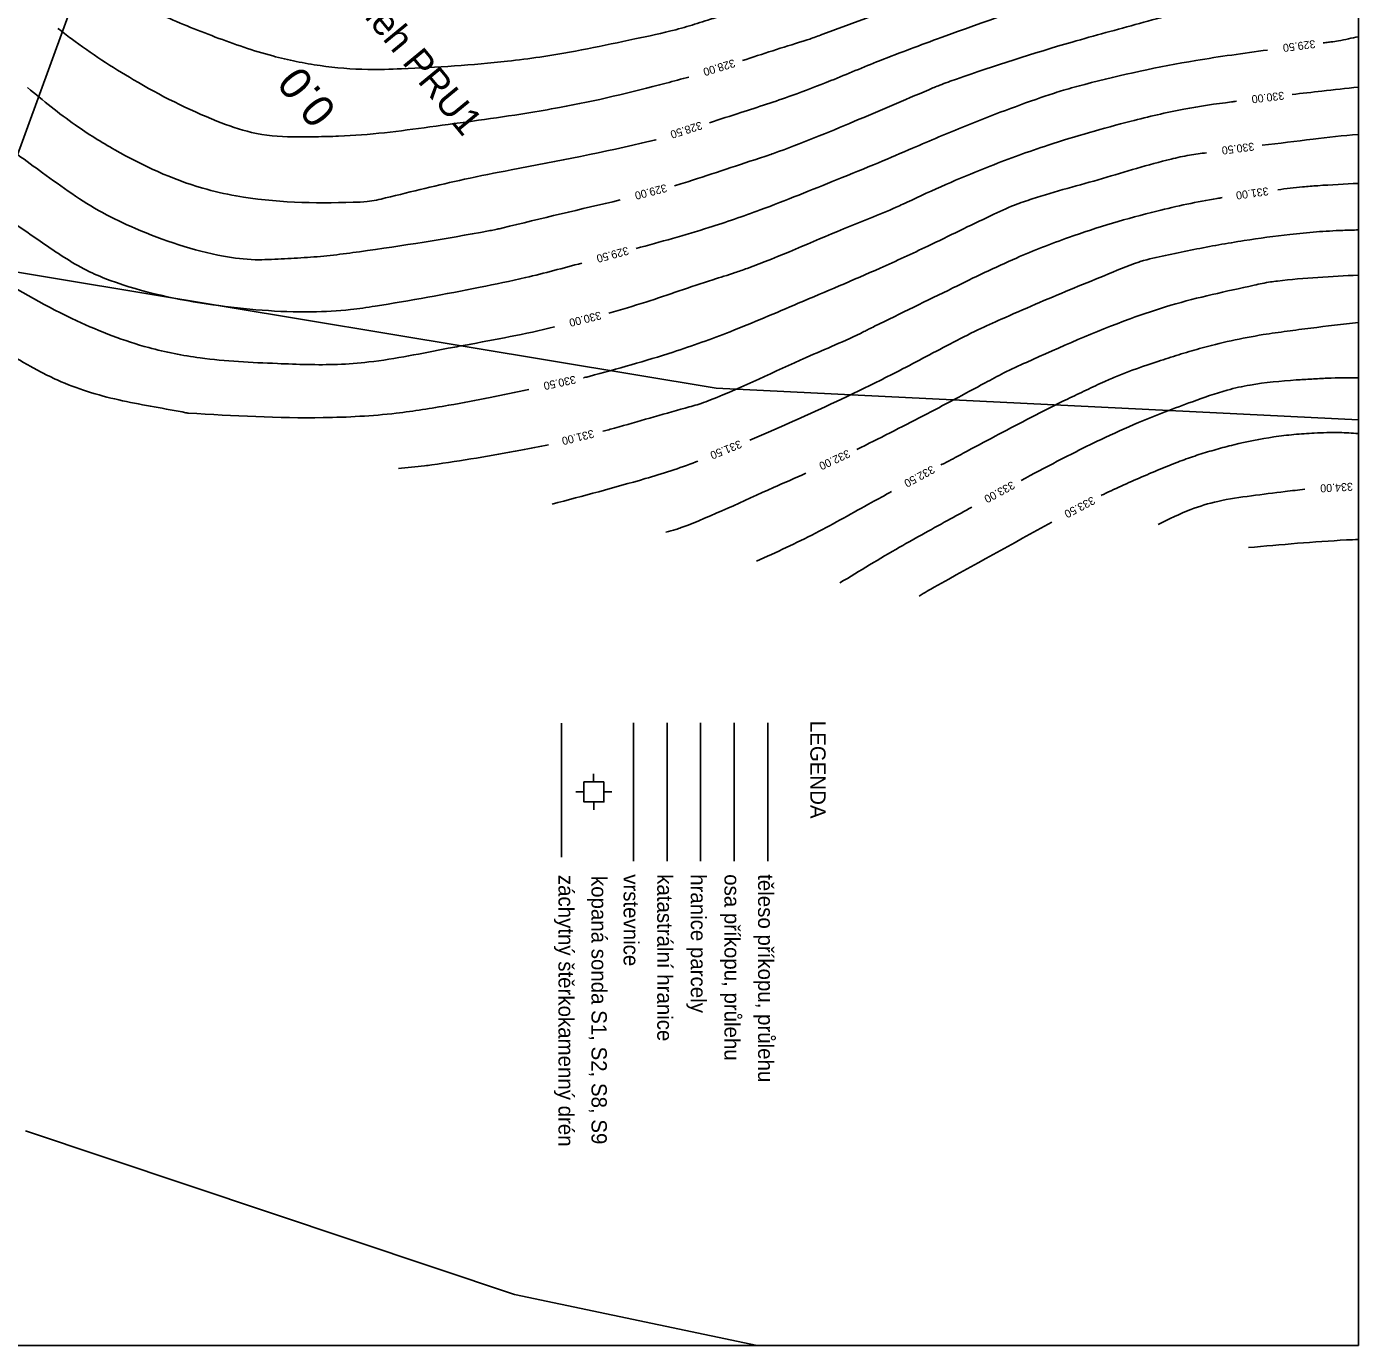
# Model space of a CAD drawing. Extents: x -564091 to -563943, y -1163604 to -1163394.
# Drawn here: x -564025.8 to -563942.6, y -1163603.9 to -1163521.5 of the extents above; entities that cross this region are included whole.
import ezdxf

# ---------------------------------------------------------------- set-up
doc = ezdxf.new("R2010")
doc.units = 0
for name, color, linetype in [('4', 7, 'Continuous'), ('_popis staničení PRU1', 7, 'Continuous'), ('_rám PRU1 a PRI1', 7, 'Continuous'), ('Hranice parcel', 7, 'Continuous'), ('Vrstva 24', 7, 'Continuous'), ('Vrstva 25', 7, 'Continuous'), ('Vrstva 26', 7, 'Continuous')]:
    doc.layers.add(name, color=color, linetype=linetype)

msp = doc.modelspace()

# ---------------------------------------------------------------- linework, layer by layer
at = {"layer": '_rám PRU1 a PRI1'}
for p, q in [((-563942.618, -1163603.908), (-563942.618, -1163393.908)), ((-563992.386, -1163565.031), (-563992.386, -1163573.399)), ((-563987.899, -1163565.001), (-563987.899, -1163573.654)), ((-563985.799, -1163565.001), (-563985.799, -1163573.654)), ((-563983.699, -1163565.001), (-563983.699, -1163573.654)), ((-563981.598, -1163565.001), (-563981.598, -1163573.654)), ((-563979.498, -1163565.001), (-563979.498, -1163573.654)), ((-563990.392, -1163568.702), (-563990.392, -1163568.202)), ((-563990.992, -1163569.315), (-563991.492, -1163569.315)), ((-563989.742, -1163569.327), (-563989.242, -1163569.327)), ((-563990.367, -1163569.952), (-563990.367, -1163570.452)), ((-564091.118, -1163603.908), (-563942.618, -1163603.908))]:
    msp.add_line(p, q, dxfattribs=at)
msp.add_lwpolyline([(-563989.742, -1163568.702), (-563989.742, -1163569.952), (-563990.992, -1163569.952), (-563990.992, -1163568.702)], close=True, dxfattribs=at)
at = {"layer": 'Hranice parcel'}
for points in [[(-564021.9, -1163513.74), (-564022.73, -1163519.5), (-564028.91, -1163536.42)], [(-564028.91, -1163536.42), (-563982.72, -1163544.1), (-563942.618, -1163546.064)], [(-563980.179, -1163603.908), (-563995.32, -1163600.73), (-564025.86, -1163590.51)]]:
    msp.add_lwpolyline(points, dxfattribs=at)
at = {"layer": 'Vrstva 24'}
for points in [[(-563981.09, -1163523.624), (-563977.297, -1163522.411), (-563977.044, -1163522.332), (-563976.888, -1163522.279), (-563976.122, -1163522.001), (-563967.965, -1163518.991), (-563964.546, -1163517.65), (-563963.719, -1163517.299), (-563962.899, -1163516.935), (-563962.079, -1163516.568), (-563961.256, -1163516.209), (-563958.806, -1163515.217), (-563955.507, -1163514.121), (-563954.271, -1163513.735), (-563953.033, -1163513.357), (-563951.794, -1163512.978), (-563950.56, -1163512.586), (-563949.842, -1163512.32), (-563948.534, -1163511.756), (-563947.231, -1163511.18), (-563945.929, -1163510.605), (-563944.62, -1163510.044), (-563942.618, -1163509.205)], [(-563985.34, -1163531.458), (-563984.8, -1163531.288), (-563980.022, -1163529.724), (-563979.493, -1163529.549), (-563979.15, -1163529.429), (-563974.083, -1163527.416), (-563969.443, -1163525.445), (-563968.766, -1163525.163), (-563967.716, -1163524.777), (-563960.498, -1163522.468), (-563958.395, -1163521.879), (-563956.289, -1163521.303), (-563954.183, -1163520.729), (-563952.079, -1163520.145), (-563951.956, -1163520.11), (-563951.901, -1163520.097), (-563950.485, -1163519.822), (-563949.067, -1163519.564), (-563946.237, -1163519.013), (-563945.87, -1163518.932)], [(-564023.856, -1163521.61), (-564023.008, -1163522.254), (-564019.131, -1163524.819), (-564013.91, -1163527.406), (-564011.75, -1163528.111), (-564009.173, -1163528.394), (-564007.742, -1163528.383), (-564006.309, -1163528.346), (-564003.45, -1163528.132), (-564000.607, -1163527.771), (-563994.561, -1163526.908), (-563992.517, -1163526.557), (-563985.848, -1163525.032), (-563984.436, -1163524.651)], [(-564027.878, -1163528.392), (-564024.804, -1163530.633), (-564021.062, -1163533.125), (-564019.008, -1163534.113), (-564013.494, -1163535.843), (-564011.523, -1163536.066), (-564009.893, -1163536.018), (-564008.263, -1163535.926), (-564006.633, -1163535.779), (-564005.008, -1163535.571), (-563996.957, -1163534.27), (-563996.575, -1163534.197), (-563996.412, -1163534.163), (-563996.109, -1163534.091), (-563988.728, -1163532.333)], [(-563947.656, -1163531.694), (-563946.1, -1163531.518), (-563945.153, -1163531.441), (-563942.618, -1163531.298)], [(-563989.803, -1163546.79), (-563989.07, -1163546.588), (-563984.665, -1163545.34), (-563983.671, -1163545.047), (-563983.074, -1163544.825), (-563977.1, -1163542.175), (-563973.501, -1163540.56), (-563973.207, -1163540.412), (-563972.833, -1163540.227), (-563967.943, -1163537.832), (-563963.975, -1163535.961), (-563960.714, -1163534.677), (-563955.196, -1163533.028), (-563951.439, -1163532.239), (-563951.12, -1163532.187)], [(-563973.953, -1163547.931), (-563969.797, -1163545.821), (-563965.936, -1163543.764), (-563964.762, -1163543.143), (-563963.355, -1163542.483), (-563956.87, -1163539.76), (-563954.339, -1163538.915), (-563949.134, -1163537.661), (-563948.106, -1163537.456), (-563947.671, -1163537.399), (-563945.146, -1163537.17), (-563942.618, -1163537.028)], [(-563963.686, -1163549.861), (-563961.428, -1163548.666), (-563958.718, -1163547.314), (-563956.348, -1163546.246), (-563952.985, -1163544.938), (-563950.812, -1163544.215), (-563949.385, -1163543.898), (-563946.504, -1163543.583), (-563945.533, -1163543.522), (-563944.561, -1163543.471), (-563942.618, -1163543.44)], [(-564002.58, -1163549.11), (-564000.945, -1163548.948), (-564000.492, -1163548.886), (-563994.936, -1163547.974), (-563993.2, -1163547.632)], [(-563985.87, -1163553.1), (-563985.25, -1163552.928), (-563984.908, -1163552.806), (-563979.147, -1163550.301), (-563977.121, -1163549.415)], [(-563955.12, -1163552.61), (-563953.083, -1163551.677), (-563951.395, -1163551.168), (-563949.299, -1163550.82), (-563947.19, -1163550.554), (-563945.956, -1163550.408)], [(-563975, -1163556.26), (-563971.274, -1163554.035), (-563968.085, -1163552.258), (-563966.761, -1163551.533)]]:
    msp.add_spline(points, degree=3, dxfattribs=at)
at = {"layer": 'Vrstva 25'}
for points in [[(-563946.757, -1163525.745), (-563944.899, -1163525.532), (-563942.618, -1163525.281)], [(-563989.43, -1163539.413), (-563987.128, -1163538.715), (-563982.94, -1163537.319), (-563981.543, -1163536.874), (-563980.802, -1163536.614), (-563974.768, -1163534.143), (-563971.48, -1163532.785), (-563971.07, -1163532.598), (-563970.515, -1163532.338), (-563965.613, -1163530.216), (-563961.995, -1163528.913), (-563956.817, -1163527.411), (-563953.518, -1163526.665), (-563950.541, -1163526.207), (-563950.231, -1163526.169)], [(-564032.089, -1163534.136), (-564031.245, -1163534.741), (-564030.045, -1163535.615), (-564028.001, -1163536.949), (-564022.663, -1163539.887), (-564018.172, -1163541.563), (-564014.964, -1163542.204), (-564010.138, -1163542.554), (-564006.379, -1163542.608), (-564004.424, -1163542.459), (-563999.466, -1163541.604), (-563998.39, -1163541.402), (-563992.828, -1163540.265), (-563992.824, -1163540.264)]]:
    msp.add_spline(points, degree=3, dxfattribs=at)
at = {"layer": 'Vrstva 26'}
for points in [[(-563983.15, -1163527.505), (-563981.18, -1163526.871), (-563977.995, -1163525.805), (-563975.558, -1163524.873), (-563972.518, -1163523.635), (-563968.669, -1163522.182), (-563960.564, -1163519.36), (-563959.897, -1163519.143), (-563959.454, -1163519.003), (-563953.72, -1163517.135), (-563950.91, -1163516.364), (-563948.203, -1163515.697), (-563943.796, -1163514.431)], [(-564021.719, -1163517.302), (-564020.817, -1163518.072), (-564019.413, -1163519.282), (-564017.985, -1163520.471), (-564017.93, -1163520.515), (-564017.522, -1163520.727), (-564015.772, -1163521.459), (-564014.015, -1163522.151), (-564010.429, -1163523.333), (-564008.953, -1163523.678), (-564007.472, -1163523.936), (-564004.488, -1163524.176), (-564002.388, -1163524.14), (-563995.764, -1163523.66), (-563993.741, -1163523.403), (-563987.81, -1163522.272), (-563985.249, -1163521.694), (-563984.562, -1163521.505), (-563983.26, -1163521.098), (-563982.321, -1163520.807)], [(-563944.817, -1163522.52), (-563944.646, -1163522.498), (-563944.333, -1163522.462), (-563943.861, -1163522.388), (-563942.618, -1163522.131)], [(-563987.732, -1163535.368), (-563983.185, -1163534.059), (-563979.983, -1163532.959), (-563975.177, -1163531.062), (-563972.582, -1163530.004), (-563970.461, -1163529.097), (-563967.171, -1163527.719), (-563962.134, -1163525.832), (-563961.042, -1163525.479), (-563959.707, -1163525.11), (-563952.769, -1163523.621), (-563948.288, -1163522.965)], [(-564025.736, -1163525.313), (-564022.765, -1163527.646), (-564020.285, -1163529.203), (-564014.801, -1163531.596), (-564012.711, -1163532.078), (-564005.394, -1163532.482), (-564004.527, -1163532.432), (-564003.377, -1163532.207), (-563998.455, -1163531.041), (-563995.544, -1163530.456), (-563986.865, -1163528.663), (-563986.497, -1163528.577), (-563986.483, -1163528.574)], [(-563948.627, -1163528.92), (-563945.451, -1163528.535), (-563942.632, -1163528.24), (-563942.618, -1163528.239)], [(-563991.009, -1163543.444), (-563990.965, -1163543.434), (-563990.665, -1163543.358), (-563985.423, -1163541.839), (-563981.86, -1163540.564), (-563977.599, -1163538.791), (-563972.486, -1163536.591), (-563969.506, -1163535.215), (-563965.562, -1163533.31), (-563964.09, -1163532.656), (-563962.987, -1163532.267), (-563958.601, -1163530.993), (-563954.319, -1163529.78), (-563953.165, -1163529.537), (-563952.096, -1163529.382)], [(-564030.197, -1163531.081), (-564029.092, -1163531.937), (-564024.668, -1163535.109), (-564021.866, -1163536.818), (-564020.576, -1163537.36), (-564014.171, -1163538.883), (-564007.989, -1163539.327), (-564005.563, -1163539.187), (-564004.03, -1163538.97), (-563997.48, -1163537.79), (-563994.638, -1163537.183), (-563991.112, -1163536.278)], [(-563980.628, -1163547.341), (-563979.451, -1163546.835), (-563974.257, -1163544.472), (-563971.506, -1163543.11), (-563968.134, -1163541.339), (-563966.377, -1163540.452), (-563964.927, -1163539.788), (-563962.794, -1163538.855), (-563960.651, -1163537.95), (-563958.496, -1163537.07), (-563956.328, -1163536.213), (-563956.032, -1163536.121), (-563954.47, -1163535.761), (-563952.904, -1163535.435), (-563949.754, -1163534.876), (-563946.892, -1163534.484), (-563946.068, -1163534.402), (-563945.243, -1163534.33), (-563943.59, -1163534.234), (-563942.618, -1163534.205)], [(-564033.729, -1163537.436), (-564033.021, -1163537.894), (-564030.846, -1163539.347), (-564027.348, -1163541.666), (-564025.545, -1163542.743), (-564024.611, -1163543.236), (-564023.65, -1163543.69), (-564019.8, -1163544.879), (-564015.845, -1163545.632), (-564015.784, -1163545.643), (-564015.694, -1163545.651), (-564007.272, -1163545.936), (-564002.709, -1163545.658), (-563999.44, -1163545.166), (-563996.847, -1163544.685), (-563994.432, -1163544.176)], [(-563968.691, -1163548.893), (-563968.065, -1163548.569), (-563967.042, -1163548.025), (-563963.079, -1163545.93), (-563960.784, -1163544.774), (-563959.625, -1163544.218), (-563958.462, -1163543.67), (-563957.689, -1163543.344), (-563955.134, -1163542.422), (-563953.841, -1163542.009), (-563952.536, -1163541.625), (-563948.556, -1163540.751), (-563947.073, -1163540.537), (-563945.59, -1163540.341), (-563942.618, -1163539.991)], [(-563958.681, -1163550.805), (-563958.541, -1163550.735), (-563957.269, -1163550.137), (-563955.98, -1163549.572), (-563954.679, -1163549.023), (-563953.631, -1163548.612), (-563952.572, -1163548.248), (-563951.497, -1163547.923), (-563950.404, -1163547.633), (-563947.899, -1163547.142), (-563946.64, -1163546.991), (-563945.375, -1163546.901), (-563943.803, -1163546.87), (-563942.618, -1163546.934)], [(-563992.98, -1163551.34), (-563987.166, -1163549.748), (-563983.993, -1163548.707), (-563983.87, -1163548.66)], [(-563980.21, -1163554.91), (-563976.527, -1163553.155), (-563973.031, -1163551.243), (-563971.771, -1163550.555)], [(-563970.06, -1163557.09), (-563969.546, -1163556.781), (-563969.105, -1163556.531), (-563961.765, -1163552.459)], [(-563949.49, -1163554.06), (-563943.362, -1163553.582), (-563942.618, -1163553.547)]]:
    msp.add_spline(points, degree=3, dxfattribs=at)

# ---------------------------------------------------------------- texts
at = {"layer": '4'}
msp.add_text('Odpadní průleh PRU1', height=1.70472, rotation=309.48875, dxfattribs=at).set_placement((-564012.789, -1163511.134))
at = {"layer": '_popis staničení PRU1'}
msp.add_text('0.0', height=2, rotation=129.05251, dxfattribs=at).set_placement((-564006.357, -1163526.718))
at = {"layer": '_rám PRU1 a PRI1'}
for s, height, p in [('LEGENDA', 0.956, (-563976.849, -1163564.88)), ('záchytný štěrkokamenný drén', 0.95596, (-563992.579, -1163574.506)), ('kopaná sonda S1, S2, S8, S9', 0.956, (-563990.517, -1163574.574)), ('vrstevnice', 0.956, (-563988.512, -1163574.465)), ('katastrální hranice', 0.956, (-563986.412, -1163574.465)), ('hranice parcely', 0.956, (-563984.312, -1163574.465)), ('osa příkopu, průlehu', 0.956, (-563982.211, -1163574.465)), ('těleso příkopu, průlehu', 0.956, (-563980.111, -1163574.465))]:
    msp.add_text(s, height=height, rotation=270, dxfattribs=at).set_placement(p)
at = {"layer": 'Vrstva 25'}
for s, rotation, p in [('329.50', 187.3578, (-563945.333, -1163522.335)), ('328.00', 197.10806, (-563981.631, -1163523.525)), ('330.00', 186.90687, (-563947.279, -1163525.56)), ('328.50', 197.77358, (-563983.691, -1163527.416)), ('330.50', 187.55811, (-563949.151, -1163528.74)), ('329.00', 194.58875, (-563985.877, -1163531.332)), ('331.00', 188.04793, (-563948.265, -1163531.534)), ('329.50', 195.08255, (-563988.27, -1163535.25)), ('330.00', 194.09938, (-563989.972, -1163539.29)), ('330.50', 192.06818, (-563991.547, -1163543.303)), ('331.00', 193.91509, (-563990.428, -1163546.684)), ('331.50', 202.13905, (-563981.261, -1163547.327)), ('332.00', 205.02765, (-563974.506, -1163547.918)), ('332.50', 208.35546, (-563969.247, -1163548.909)), ('333.00', 208.50123, (-563964.248, -1163549.884)), ('334.00', 183.18016, (-563942.971, -1163549.999)), ('333.50', 207.85097, (-563959.232, -1163550.842))]:
    msp.add_text(s, height=0.5, rotation=rotation, dxfattribs=at).set_placement(p)

doc.saveas('drawing.dxf')
